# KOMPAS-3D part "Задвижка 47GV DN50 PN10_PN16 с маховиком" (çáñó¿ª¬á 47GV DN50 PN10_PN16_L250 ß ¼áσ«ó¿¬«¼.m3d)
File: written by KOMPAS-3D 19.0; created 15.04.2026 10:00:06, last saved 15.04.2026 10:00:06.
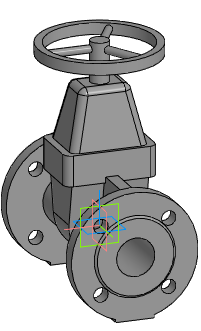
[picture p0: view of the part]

Document properties: Автор: Евгений; Полное имя файла: Z:\3.Личные\kachalov\3d для проектировщиков\2.1 Тип 47GV, 47GV.Z\Задвижка 47GV_DN40-DN600\stp_Задвижка 47GV\Задвижка 47GV DN50 PN10_PN16_L250 с маховиком.m3d

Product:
- Part/product: Задвижка 47GV DN50 PN10_PN16 с маховиком

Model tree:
1. Операция без истории:1  (labels: Задвижка 47GV DN50 PN10_PN16 с маховиком)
